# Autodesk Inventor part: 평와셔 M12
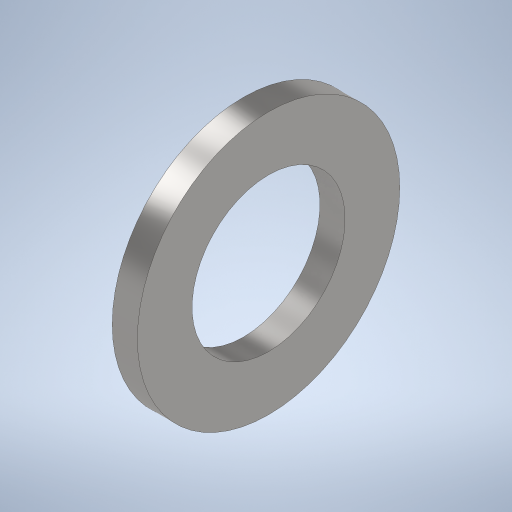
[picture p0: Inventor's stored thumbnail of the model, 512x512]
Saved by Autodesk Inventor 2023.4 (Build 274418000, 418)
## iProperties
Created: 2024-04
Part Number: 평와셔 M12
Material: 강철, 연강
Description: 평면 와셔
Document SubType Name: Modeling
Designer: Edu03
Density: 7.85 g/cm^3
Appearance: 기본값
Author: jhkim
Sending System: Autodesk Inventor 2025
Preprocessor: ST-DEVELOPER v20
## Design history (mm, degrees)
feature "Solid1"
node "솔리드1"
